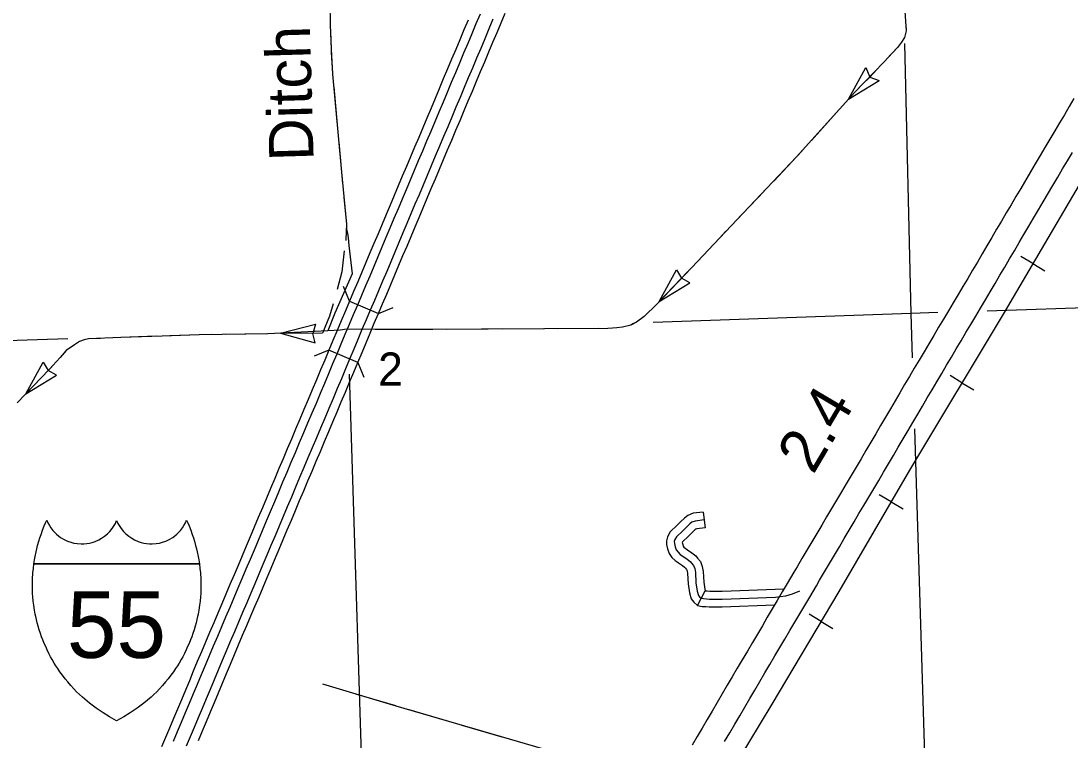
# Model space of a CAD drawing. Extents: x -117616 to 64730, y 54117 to 789866.
# Drawn here: x 63230.7 to 63430.7, y 55099.4 to 55236.4 of the extents above; entities that cross this region are included whole.
import ezdxf

# ---------------------------------------------------------------- set-up
doc = ezdxf.new("R2010")
doc.units = 0
for name, color, linetype in [('10', 7, 'Continuous'), ('19', 7, 'Continuous'), ('23', 7, 'Continuous'), ('39', 7, 'Continuous'), ('40', 7, 'Continuous'), ('43', 7, 'Continuous'), ('45', 7, 'Continuous'), ('48', 7, 'Continuous'), ('5', 7, 'Continuous')]:
    doc.layers.add(name, color=color, linetype=linetype)

msp = doc.modelspace()

# ---------------------------------------------------------------- linework, layer by layer
at = {"layer": '10'}
for points in [[(63431.46, 55221.66), (63430.55, 55220.11), (63429.63, 55218.55), (63428.72, 55217), (63427.8, 55215.46), (63426.86, 55213.89), (63425.93, 55212.32), (63425, 55210.76), (63424.08, 55209.2), (63423.15, 55207.64), (63421.3, 55204.51), (63420.38, 55202.95), (63419.46, 55201.39), (63418.54, 55199.83), (63417.63, 55198.28), (63416.71, 55196.73), (63415.78, 55195.17), (63414.86, 55193.6), (63413.95, 55192.04), (63413.04, 55190.49), (63412.12, 55188.94), (63411.21, 55187.38), (63410.29, 55185.83), (63409.37, 55184.28), (63408.44, 55182.73), (63407.51, 55181.17), (63406.58, 55179.6), (63405.65, 55178.05), (63404.72, 55176.49), (63403.79, 55174.93), (63402.87, 55173.37), (63401.94, 55171.81), (63401.01, 55170.24), (63400.1, 55168.68), (63399.18, 55167.14), (63398.27, 55165.59), (63397.37, 55164.05), (63396.45, 55162.5), (63395.53, 55160.95), (63394.6, 55159.38), (63393.66, 55157.79), (63392.72, 55156.2), (63391.79, 55154.61), (63390.86, 55153.02), (63389.92, 55151.43), (63388.98, 55149.84), (63388.05, 55148.27), (63387.11, 55146.69), (63386.17, 55145.11), (63385.24, 55143.53), (63384.3, 55141.95), (63383.36, 55140.36), (63382.42, 55138.78), (63381.48, 55137.19), (63380.54, 55135.59), (63379.6, 55133.99), (63378.66, 55132.41), (63378.06, 55131.39), (63376.78, 55129.23), (63375.84, 55127.65), (63374.88, 55126.04), (63373.93, 55124.42), (63372.98, 55122.81), (63372.05, 55121.21), (63371.1, 55119.61), (63370.15, 55117.99), (63369.19, 55116.37), (63368.23, 55114.74), (63367.28, 55113.12), (63366.32, 55111.5), (63365.36, 55109.87), (63364.39, 55108.22), (63363.43, 55106.59), (63362.48, 55104.96), (63361.52, 55103.34), (63360.56, 55101.72), (63359.6, 55100.1), (63358.65, 55098.49)], [(63364.86, 55099.17), (63365.82, 55100.79), (63366.78, 55102.43), (63367.75, 55104.06), (63368.7, 55105.69), (63369.66, 55107.33), (63370.63, 55108.96), (63371.59, 55110.58), (63372.54, 55112.21), (63373.5, 55113.83), (63374.45, 55115.45), (63375.41, 55117.07), (63376.36, 55118.68), (63377.3, 55120.28), (63378.24, 55121.89), (63379.18, 55123.49), (63380.13, 55125.09), (63381.08, 55126.68), (63382.36, 55128.84), (63382.97, 55129.86), (63383.9, 55131.45), (63384.84, 55133.05), (63385.79, 55134.64), (63386.73, 55136.23), (63387.66, 55137.82), (63388.6, 55139.4), (63389.54, 55140.98), (63390.47, 55142.56), (63391.41, 55144.14), (63392.35, 55145.72), (63393.29, 55147.3), (63394.23, 55148.89), (63395.16, 55150.48), (63396.1, 55152.08), (63397.03, 55153.66), (63397.97, 55155.25), (63398.9, 55156.83), (63399.83, 55158.4), (63400.75, 55159.95), (63401.67, 55161.5), (63402.58, 55163.05), (63403.49, 55164.6), (63404.41, 55166.15), (63405.32, 55167.7), (63406.24, 55169.26), (63407.17, 55170.82), (63408.09, 55172.37), (63409.02, 55173.93), (63409.94, 55175.49), (63410.87, 55177.05), (63411.8, 55178.61), (63412.74, 55180.17), (63413.66, 55181.72), (63414.59, 55183.28), (63415.51, 55184.84), (63416.43, 55186.4), (63417.35, 55187.96), (63418.26, 55189.51), (63419.17, 55191.07), (63420.09, 55192.63), (63421.01, 55194.18), (63421.93, 55195.73), (63422.85, 55197.3), (63423.77, 55198.86), (63424.69, 55200.41), (63425.6, 55201.97), (63427.45, 55205.09), (63428.38, 55206.65), (63429.3, 55208.21), (63430.23, 55209.77), (63431.16, 55211.33)]]:
    msp.add_lwpolyline(points, dxfattribs=at)
at = {"layer": '19'}
for points in [[(63315.96, 55236.56), (63315.17, 55234.7), (63314.39, 55232.83), (63313.61, 55230.98), (63312.82, 55229.13), (63312.03, 55227.26), (63311.23, 55225.38), (63310.45, 55223.51), (63309.67, 55221.64), (63308.89, 55219.78), (63308.11, 55217.92), (63307.32, 55216.06), (63306.53, 55214.21), (63305.74, 55212.36), (63304.96, 55210.51), (63304.18, 55208.66), (63303.4, 55206.82), (63302.63, 55204.99), (63301.87, 55203.16), (63301.1, 55201.34), (63300.32, 55199.52), (63299.55, 55197.69), (63298.78, 55195.87), (63298.01, 55194.05), (63297.23, 55192.22), (63296.46, 55190.38), (63295.69, 55188.54), (63294.91, 55186.71), (63294.13, 55184.87), (63293.35, 55183.02), (63292.55, 55181.17), (63291.76, 55179.29), (63290.97, 55177.42), (63290.19, 55175.55), (63289.41, 55173.68), (63288.62, 55171.8), (63287.83, 55169.93), (63287.04, 55168.05), (63286.25, 55166.17), (63285.46, 55164.29), (63284.66, 55162.41), (63283.86, 55160.53), (63283.07, 55158.65), (63282.27, 55156.77), (63281.47, 55154.89), (63280.67, 55153), (63279.88, 55151.13), (63279.08, 55149.25), (63278.3, 55147.37), (63277.51, 55145.51), (63276.73, 55143.66), (63275.96, 55141.82), (63275.18, 55139.98), (63274.41, 55138.16), (63273.64, 55136.34), (63272.87, 55134.53), (63272.1, 55132.71), (63271.33, 55130.89), (63270.56, 55129.07), (63269.79, 55127.25), (63269.01, 55125.41), (63268.23, 55123.58), (63267.45, 55121.74), (63266.66, 55119.91), (63265.88, 55118.07), (63265.1, 55116.22), (63264.33, 55114.39), (63263.57, 55112.56), (63262.81, 55110.74), (63262.05, 55108.93), (63261.29, 55107.12), (63260.53, 55105.32), (63259.77, 55103.52), (63259.01, 55101.72), (63258.25, 55099.92), (63257.49, 55098.12)], [(63259.82, 55099.25), (63260.58, 55101.05), (63261.34, 55102.85), (63262.1, 55104.66), (63262.86, 55106.46), (63263.62, 55108.27), (63264.38, 55110.09), (63265.14, 55111.91), (63265.9, 55113.73), (63266.67, 55115.57), (63267.44, 55117.4), (63268.23, 55119.24), (63269.01, 55121.07), (63269.79, 55122.91), (63270.58, 55124.75), (63271.35, 55126.58), (63272.13, 55128.41), (63272.9, 55130.23), (63273.67, 55132.05), (63274.44, 55133.86), (63275.21, 55135.68), (63275.98, 55137.5), (63276.75, 55139.32), (63277.52, 55141.16), (63278.3, 55143), (63279.08, 55144.85), (63279.86, 55146.72), (63280.65, 55148.59), (63281.44, 55150.46), (63282.24, 55152.34), (63283.03, 55154.22), (63283.83, 55156.11), (63284.63, 55157.99), (63285.43, 55159.87), (63286.23, 55161.75), (63287.02, 55163.63), (63287.82, 55165.51), (63288.61, 55167.39), (63289.4, 55169.27), (63290.19, 55171.15), (63290.98, 55173.02), (63291.76, 55174.89), (63292.54, 55176.76), (63293.33, 55178.63), (63294.12, 55180.5), (63294.91, 55182.36), (63295.7, 55184.2), (63296.48, 55186.04), (63297.26, 55187.88), (63298.03, 55189.72), (63298.8, 55191.56), (63299.57, 55193.39), (63300.35, 55195.21), (63301.12, 55197.03), (63301.89, 55198.86), (63302.66, 55200.68), (63303.43, 55202.5), (63304.2, 55204.33), (63304.97, 55206.16), (63305.74, 55208), (63306.52, 55209.84), (63307.31, 55211.69), (63308.1, 55213.55), (63308.89, 55215.4), (63309.67, 55217.26), (63310.46, 55219.12), (63311.24, 55220.99), (63312.02, 55222.85), (63312.8, 55224.72), (63313.59, 55226.6), (63314.38, 55228.46), (63315.17, 55230.32), (63315.96, 55232.17), (63316.74, 55234.04), (63317.52, 55235.9), (63318.31, 55237.75)], [(63320.7, 55236.73), (63319.92, 55234.88), (63319.14, 55233.03), (63318.35, 55231.17), (63317.57, 55229.3), (63316.78, 55227.44), (63315.98, 55225.58), (63315.2, 55223.72), (63314.42, 55221.85), (63313.64, 55219.98), (63312.85, 55218.11), (63312.07, 55216.25), (63311.28, 55214.38), (63310.49, 55212.53), (63309.7, 55210.68), (63308.92, 55208.83), (63308.14, 55206.99), (63307.37, 55205.15), (63306.6, 55203.32), (63305.83, 55201.49), (63305.06, 55199.66), (63304.28, 55197.84), (63303.51, 55196.02), (63302.74, 55194.2), (63301.97, 55192.37), (63301.2, 55190.55), (63300.43, 55188.71), (63299.65, 55186.87), (63298.87, 55185.03), (63298.09, 55183.18), (63297.3, 55181.34), (63296.51, 55179.48), (63295.72, 55177.63), (63294.94, 55175.76), (63294.16, 55173.89), (63293.37, 55172.01), (63292.59, 55170.14), (63291.8, 55168.26), (63291.01, 55166.38), (63290.21, 55164.5), (63289.42, 55162.61), (63288.62, 55160.73), (63287.82, 55158.85), (63287.02, 55156.97), (63286.22, 55155.09), (63285.43, 55153.21), (63284.63, 55151.33), (63283.84, 55149.45), (63283.04, 55147.58), (63282.26, 55145.71), (63281.48, 55143.85), (63280.7, 55141.99), (63279.92, 55140.15), (63279.15, 55138.31), (63278.37, 55136.48), (63277.6, 55134.66), (63276.83, 55132.85), (63276.06, 55131.03), (63275.29, 55129.22), (63274.52, 55127.39), (63273.75, 55125.57), (63272.97, 55123.73), (63272.19, 55121.89), (63271.4, 55120.05), (63270.62, 55118.22), (63269.83, 55116.39), (63269.06, 55114.56), (63268.3, 55112.73), (63267.54, 55110.91), (63266.78, 55109.08), (63266.02, 55107.27), (63265.26, 55105.45), (63264.5, 55103.65), (63263.73, 55101.84), (63262.97, 55100.04), (63262.21, 55098.24)], [(63264.54, 55099.38), (63265.3, 55101.18), (63266.06, 55102.99), (63266.82, 55104.8), (63267.59, 55106.61), (63268.35, 55108.43), (63269.11, 55110.25), (63269.87, 55112.08), (63270.63, 55113.9), (63271.4, 55115.72), (63272.18, 55117.55), (63272.97, 55119.39), (63273.75, 55121.23), (63274.53, 55123.07), (63275.31, 55124.9), (63276.09, 55126.73), (63276.86, 55128.55), (63277.63, 55130.37), (63278.4, 55132.18), (63279.17, 55134), (63279.94, 55135.82), (63280.71, 55137.65), (63281.49, 55139.49), (63282.26, 55141.33), (63283.04, 55143.19), (63283.83, 55145.05), (63284.61, 55146.92), (63285.4, 55148.79), (63286.2, 55150.67), (63286.99, 55152.55), (63287.79, 55154.42), (63288.59, 55156.3), (63289.39, 55158.19), (63290.18, 55160.07), (63290.98, 55161.95), (63291.78, 55163.84), (63292.57, 55165.72), (63293.37, 55167.6), (63294.15, 55169.48), (63294.94, 55171.36), (63295.73, 55173.23), (63296.51, 55175.1), (63297.29, 55176.97), (63298.07, 55178.82), (63298.86, 55180.67), (63299.65, 55182.52), (63300.44, 55184.37), (63301.22, 55186.21), (63301.99, 55188.05), (63302.76, 55189.89), (63303.53, 55191.71), (63304.31, 55193.53), (63305.08, 55195.36), (63305.85, 55197.18), (63306.62, 55199), (63307.4, 55200.83), (63308.17, 55202.66), (63308.94, 55204.5), (63309.71, 55206.33), (63310.48, 55208.17), (63311.26, 55210.01), (63312.05, 55211.86), (63312.84, 55213.72), (63313.63, 55215.59), (63314.42, 55217.45), (63315.21, 55219.33), (63315.99, 55221.19), (63316.77, 55223.06), (63317.55, 55224.92), (63318.34, 55226.78), (63319.13, 55228.64), (63319.92, 55230.51), (63320.7, 55232.37), (63321.49, 55234.22), (63322.27, 55236.07), (63323.05, 55237.91)]]:
    msp.add_lwpolyline(points, dxfattribs=at)
at = {"layer": '23'}
for points in [[(63233.18, 55133), (63233.3, 55133.75), (63233.42, 55134.42), (63233.6, 55135.28), (63233.73, 55135.84), (63233.89, 55136.5), (63234.11, 55137.29), (63234.32, 55137.94), (63234.54, 55138.61), (63234.84, 55139.44), (63235.15, 55140.22), (63235.41, 55140.82), (63235.62, 55141.29), (63235.85, 55140.78), (63236.12, 55140.29), (63236.42, 55139.85), (63236.8, 55139.35), (63237.1, 55139.01), (63237.48, 55138.65), (63237.86, 55138.33), (63238.27, 55138.03), (63238.93, 55137.64), (63239.6, 55137.33), (63240.2, 55137.11), (63240.8, 55136.96), (63241.45, 55136.85), (63242.2, 55136.8), (63242.69, 55136.81), (63243.25, 55136.87), (63243.76, 55136.95), (63244.3, 55137.08), (63244.84, 55137.26), (63245.57, 55137.58), (63246.07, 55137.87), (63246.66, 55138.27), (63247.22, 55138.74), (63247.63, 55139.15), (63248.09, 55139.72), (63248.48, 55140.3), (63248.71, 55140.7), (63248.95, 55141.23)], [(63248.95, 55141.23), (63249.2, 55140.7), (63249.43, 55140.3), (63249.82, 55139.72), (63250.28, 55139.15), (63250.69, 55138.74), (63251.25, 55138.27), (63251.84, 55137.87), (63252.34, 55137.58), (63253.07, 55137.26), (63253.61, 55137.08), (63254.15, 55136.95), (63254.65, 55136.87), (63255.22, 55136.81), (63255.71, 55136.8), (63256.46, 55136.85), (63257.1, 55136.96), (63257.7, 55137.11), (63258.31, 55137.33), (63258.98, 55137.64), (63259.64, 55138.03), (63260.05, 55138.33), (63260.43, 55138.65), (63260.8, 55139.01), (63261.11, 55139.35), (63261.49, 55139.85), (63261.79, 55140.29), (63262.05, 55140.78), (63262.29, 55141.29), (63262.5, 55140.82), (63262.76, 55140.22), (63263.07, 55139.44), (63263.37, 55138.61), (63263.59, 55137.94), (63263.8, 55137.29), (63264.01, 55136.5), (63264.18, 55135.84), (63264.31, 55135.28), (63264.49, 55134.42), (63264.61, 55133.75), (63264.72, 55133)], [(63248.95, 55103.12), (63247.57, 55103.86), (63246.36, 55104.59), (63245.02, 55105.5), (63243.77, 55106.44), (63242.41, 55107.6), (63241.9, 55108.08), (63241.32, 55108.64), (63240.78, 55109.2), (63240.19, 55109.84), (63239.62, 55110.51), (63239.13, 55111.11), (63238.61, 55111.79), (63238.14, 55112.44), (63237.73, 55113.05), (63237.37, 55113.6), (63237.07, 55114.08), (63236.67, 55114.76), (63236.37, 55115.31), (63236.03, 55115.95), (63235.7, 55116.62), (63235.42, 55117.24), (63235.16, 55117.83), (63234.88, 55118.5), (63234.65, 55119.12), (63234.42, 55119.76), (63234.2, 55120.44), (63233.99, 55121.13), (63233.81, 55121.79), (63233.66, 55122.42), (63233.53, 55122.98), (63233.44, 55123.39), (63233.29, 55124.19), (63233.15, 55125.12), (63233.05, 55125.89), (63232.98, 55126.71), (63232.94, 55127.37), (63232.91, 55128.2), (63232.9, 55128.98), (63232.91, 55129.85), (63232.94, 55130.42), (63232.97, 55130.94), (63232.99, 55131.27), (63233.08, 55132.13), (63233.18, 55133)], [(63233.18, 55133), (63264.72, 55133)], [(63264.72, 55133), (63233.18, 55133)], [(63264.72, 55133), (63264.83, 55132.13), (63264.92, 55131.27), (63264.94, 55130.94), (63264.97, 55130.42), (63265, 55129.85), (63265.01, 55128.98), (63265, 55128.2), (63264.97, 55127.37), (63264.93, 55126.71), (63264.86, 55125.89), (63264.76, 55125.12), (63264.62, 55124.19), (63264.47, 55123.39), (63264.38, 55122.98), (63264.25, 55122.42), (63264.1, 55121.79), (63263.92, 55121.13), (63263.71, 55120.44), (63263.49, 55119.76), (63263.26, 55119.12), (63263.02, 55118.5), (63262.75, 55117.83), (63262.49, 55117.24), (63262.21, 55116.62), (63261.88, 55115.95), (63261.54, 55115.31), (63261.24, 55114.76), (63260.84, 55114.08), (63260.54, 55113.6), (63260.18, 55113.05), (63259.77, 55112.44), (63259.3, 55111.79), (63258.78, 55111.11), (63258.29, 55110.51), (63257.72, 55109.84), (63257.13, 55109.2), (63256.59, 55108.64), (63256.01, 55108.08), (63255.5, 55107.6), (63254.14, 55106.44), (63252.89, 55105.5), (63251.55, 55104.59), (63250.34, 55103.86), (63248.95, 55103.12)]]:
    msp.add_lwpolyline(points, dxfattribs=at)
at = {"layer": '39'}
for p, q in [((63293.35, 55183.02), (63292.22, 55185.8)), ((63293.35, 55183.02), (63298.87, 55180.69)), ((63298.87, 55180.69), (63301.65, 55181.82)), ((63289.41, 55173.67), (63286.63, 55172.54)), ((63294.94, 55171.36), (63289.41, 55173.67)), ((63294.94, 55171.36), (63296.08, 55168.58))]:
    msp.add_line(p, q, dxfattribs=at)
at = {"layer": '40'}
for p, q in [((63423.61, 55190.18), (63421.34, 55191.52)), ((63423.61, 55190.18), (63425.88, 55188.84)), ((63410.1, 55167.5), (63407.84, 55168.85)), ((63410.1, 55167.5), (63412.37, 55166.14)), ((63396.6, 55144.81), (63394.32, 55146.14)), ((63396.6, 55144.81), (63398.88, 55143.48)), ((63383.24, 55122.04), (63380.97, 55123.39)), ((63383.24, 55122.04), (63385.51, 55120.69))]:
    msp.add_line(p, q, dxfattribs=at)
for points in [[(63497.11, 55314.94), (63494.89, 55311.15), (63488.19, 55299.73), (63486.63, 55297.09), (63484.35, 55293.36), (63480.84, 55287.75), (63474.86, 55277.55), (63472.91, 55274.32), (63459.75, 55252.17), (63453.09, 55240.87), (63451.71, 55238.38), (63449.77, 55234.97), (63444.13, 55224.89), (63441.27, 55220.19), (63436.54, 55212.09), (63418.12, 55180.88), (63400.11, 55150.82), (63386.64, 55127.75), (63373.86, 55106.28), (63362.71, 55087.83), (63354.73, 55074.34)], [(63497.11, 55314.94), (63494.89, 55311.15), (63488.19, 55299.73), (63486.63, 55297.09), (63484.35, 55293.36), (63480.84, 55287.75), (63474.86, 55277.55), (63472.91, 55274.32), (63459.75, 55252.17), (63453.09, 55240.87), (63451.71, 55238.38), (63449.77, 55234.97), (63444.13, 55224.89), (63441.27, 55220.19), (63436.54, 55212.09), (63418.12, 55180.88), (63400.11, 55150.82), (63386.64, 55127.75), (63373.86, 55106.28), (63362.71, 55087.83), (63355.07, 55074.27)]]:
    msp.add_lwpolyline(points, dxfattribs=at)
at = {"layer": '43'}
for p, q in [((63388.47, 55221.5), (63391.75, 55227.53)), ((63391.75, 55227.53), (63392.53, 55225.72)), ((63388.47, 55221.5), (63394.33, 55225.08)), ((63392.53, 55225.72), (63394.33, 55225.08)), ((63352.4, 55182.95), (63355.68, 55188.98)), ((63355.68, 55188.98), (63356.63, 55187.42)), ((63352.4, 55182.95), (63358.25, 55186.53)), ((63358.25, 55186.53), (63356.65, 55187.4)), ((63280.21, 55176.95), (63286.86, 55178.65)), ((63286.86, 55178.65), (63286.36, 55176.89)), ((63280.21, 55176.95), (63286.82, 55175.09)), ((63286.82, 55175.09), (63286.36, 55176.86)), ((63231.62, 55165.37), (63234.92, 55171.39)), ((63234.92, 55171.39), (63235.87, 55169.83)), ((63231.62, 55165.37), (63237.49, 55168.94)), ((63237.49, 55168.94), (63235.89, 55169.81))]:
    msp.add_line(p, q, dxfattribs=at)
for points in [[(63288.29, 55314.94), (63288.51, 55306.96), (63288.93, 55288.45), (63289.12, 55283.22), (63289.02, 55278.57), (63289.31, 55256.35), (63289.59, 55239.99), (63289.66, 55235.68), (63289.82, 55231.01), (63290.13, 55226.27), (63291.84, 55207.62), (63292.74, 55197.67), (63292.76, 55196.74), (63292.95, 55196.01), (63293.07, 55195.09), (63293.21, 55193.63), (63293.85, 55188.22), (63290.53, 55180.74), (63289.19, 55177.36)], [(63399.14, 55239.17), (63399.47, 55234.52), (63399.14, 55233.23), (63398.6, 55232.38), (63397.83, 55231.38), (63395.18, 55228.55), (63389.7, 55222.86), (63378.56, 55210.5), (63363.85, 55195.01), (63358.58, 55189.45), (63351.95, 55182.47), (63349.5, 55180.14), (63348.07, 55179.04), (63346.95, 55178.47), (63345.36, 55178.11), (63344.3, 55177.96), (63342.58, 55177.85), (63306.43, 55177.62), (63298.26, 55177.62), (63292.82, 55177.69), (63291.54, 55177.49), (63289.19, 55177.36), (63277.76, 55176.84), (63264.68, 55176.62), (63257.61, 55176.39), (63249.76, 55176.13), (63243.57, 55175.85), (63242.73, 55175.67), (63241.87, 55175.36), (63240.89, 55174.69), (63239.35, 55173.65), (63238.19, 55172.28), (63236.08, 55170.03), (63229.97, 55163.64)], [(63399.14, 55239.17), (63399.47, 55234.52), (63399.14, 55233.23), (63398.6, 55232.38), (63397.83, 55231.38), (63395.18, 55228.55), (63389.7, 55222.86), (63378.56, 55210.5), (63363.85, 55195.01), (63358.58, 55189.45), (63351.95, 55182.47), (63349.5, 55180.14), (63348.07, 55179.04), (63346.95, 55178.47), (63345.36, 55178.11), (63344.3, 55177.96), (63342.58, 55177.85), (63306.43, 55177.62), (63298.26, 55177.62), (63292.82, 55177.69), (63291.54, 55177.49), (63289.19, 55177.36), (63277.76, 55176.84), (63264.68, 55176.62), (63257.61, 55176.39), (63249.76, 55176.13), (63243.57, 55175.85), (63242.73, 55175.67), (63241.87, 55175.36), (63240.89, 55174.69), (63239.35, 55173.65), (63238.19, 55172.28), (63236.08, 55170.03), (63229.97, 55163.64)], [(63289.71, 55234.38), (63289.82, 55231.01), (63289.86, 55230.42)], [(63399.38, 55235.78), (63399.47, 55234.52), (63399.14, 55233.23), (63398.6, 55232.38), (63397.83, 55231.38), (63395.74, 55229.15)], [(63289.86, 55230.42), (63290.12, 55226.47)], [(63393.92, 55227.24), (63392.53, 55225.72), (63391.17, 55224.39)], [(63391.17, 55224.39), (63389.7, 55222.86), (63388.47, 55221.5)], [(63290.36, 55223.84), (63291.08, 55215.95)], [(63386.7, 55219.54), (63381.4, 55213.65)], [(63291.32, 55213.33), (63291.84, 55207.62), (63292.03, 55205.44)], [(63379.64, 55211.69), (63378.56, 55210.5), (63374.21, 55205.92)], [(63292.27, 55202.81), (63292.74, 55197.67), (63292.62, 55194.75), (63292.63, 55194.6)], [(63372.4, 55204), (63366.94, 55198.26)], [(63365.12, 55196.35), (63363.85, 55195.01), (63359.67, 55190.6)], [(63292.33, 55192.59), (63291.86, 55188.65), (63290.97, 55185.28)], [(63357.86, 55188.68), (63352.4, 55182.95)], [(63290.21, 55182.52), (63289.52, 55180.18), (63288.19, 55176.97)], [(63350.51, 55181.1), (63349.5, 55180.14), (63348.07, 55179.04), (63347.39, 55178.7)], [(63347.39, 55178.7), (63346.95, 55178.47), (63345.36, 55178.11), (63344.3, 55177.96), (63343.54, 55177.91)], [(63256.46, 55176.35), (63249.76, 55176.13), (63248.54, 55176.08)], [(63267.01, 55176.66), (63264.68, 55176.62), (63259.09, 55176.44)], [(63277.57, 55176.84), (63269.65, 55176.7)], [(63286.36, 55176.89), (63280.21, 55176.95)], [(63288.19, 55176.97), (63286.36, 55176.89)], [(63309.22, 55177.64), (63306.43, 55177.62), (63301.3, 55177.62)], [(63319.78, 55177.71), (63311.86, 55177.66)], [(63330.34, 55177.78), (63322.42, 55177.73)], [(63340.9, 55177.84), (63332.98, 55177.79)], [(63245.9, 55175.95), (63243.57, 55175.85), (63242.73, 55175.67), (63241.87, 55175.36), (63240.89, 55174.69), (63239.35, 55173.65), (63238.85, 55173.07)], [(63237.09, 55171.11), (63236.08, 55170.03), (63231.62, 55165.37)], [(63288.18, 55110.14), (63302.18, 55105.97), (63330.31, 55097.73), (63333.12, 55097), (63335.03, 55096.58), (63338.54, 55095.7), (63341.4, 55095.01), (63345.27, 55093.85), (63347.92, 55092.82), (63349.95, 55091.96), (63351.49, 55091.3), (63352.84, 55090.59), (63354.11, 55089.85), (63355.66, 55089.25), (63356.61, 55089.01), (63359.11, 55088.76), (63360.09, 55088.61), (63361.22, 55088.49), (63362.29, 55088.2), (63362.29, 55088.04), (63363.64, 55087.17)], [(63288.18, 55110.14), (63291.98, 55109.01)], [(63294.51, 55108.26), (63302.1, 55106)], [(63304.63, 55105.25), (63312.23, 55103.03)], [(63314.77, 55102.28), (63322.37, 55100.06)]]:
    msp.add_lwpolyline(points, dxfattribs=at)
at = {"layer": '45'}
for p, q in [((63360.77, 55142.85), (63361.13, 55139.87)), ((63359.7, 55125.08), (63361.17, 55127.86))]:
    msp.add_line(p, q, dxfattribs=at)
for points in [[(63360.77, 55142.85), (63358.85, 55142.62), (63357.83, 55142.22), (63357.22, 55141.72), (63356.46, 55141), (63355.84, 55140.34), (63354.46, 55139.1), (63353.95, 55138.16), (63353.77, 55137.39), (63353.8, 55136.69), (63353.99, 55135.85), (63354.29, 55134.98), (63354.82, 55134.23), (63355.42, 55133.65), (63355.8, 55133.38)], [(63360.95, 55141.36), (63359.22, 55141.15), (63358.6, 55140.91), (63358.22, 55140.6), (63357.52, 55139.94), (63356.88, 55139.26), (63355.66, 55138.15), (63355.36, 55137.62), (63355.27, 55137.25), (63355.29, 55136.89), (63355.43, 55136.27), (63355.64, 55135.68), (63355.97, 55135.21), (63356.38, 55134.81), (63356.92, 55134.43), (63357.71, 55133.9), (63358.29, 55133.45), (63358.55, 55133.12), (63358.93, 55132.67), (63359.15, 55132.1), (63359.29, 55131.35), (63359.39, 55129.35), (63359.62, 55127.82), (63359.86, 55126.99), (63360.07, 55126.72), (63360.36, 55126.47), (63360.8, 55126.39), (63361.96, 55126.3), (63364.4, 55126.3), (63374.56, 55126.67), (63375.46, 55126.78), (63376.53, 55126.91), (63377.78, 55127.26), (63379.2, 55127.85)], [(63361.13, 55139.87), (63359.59, 55139.68), (63359.36, 55139.6), (63359.21, 55139.47), (63358.59, 55138.88), (63357.93, 55138.19), (63356.85, 55137.21), (63356.78, 55137.09), (63356.78, 55137.09), (63356.87, 55136.68), (63356.98, 55136.37), (63357.11, 55136.19), (63357.34, 55135.97), (63357.54, 55135.83)], [(63357.54, 55135.83), (63357.77, 55135.67), (63358.6, 55135.11), (63359.35, 55134.52), (63359.7, 55134.08), (63360.23, 55133.45), (63360.6, 55132.51), (63360.78, 55131.53), (63360.89, 55129.5), (63361.09, 55128.15), (63361.17, 55127.86), (63361.51, 55127.84)], [(63355.8, 55133.38), (63356.07, 55133.2), (63356.83, 55132.68), (63357.22, 55132.37), (63357.39, 55132.17), (63357.62, 55131.9), (63357.7, 55131.68), (63357.8, 55131.17), (63357.9, 55129.2), (63358.15, 55127.5), (63358.5, 55126.31), (63358.98, 55125.67), (63359.7, 55125.08), (63360.59, 55124.9), (63361.29, 55124.85)], [(63361.51, 55127.84), (63362.01, 55127.8), (63364.37, 55127.8), (63376.18, 55128.23)], [(63361.29, 55124.85), (63361.9, 55124.8), (63364.42, 55124.8), (63374.36, 55125.16)]]:
    msp.add_lwpolyline(points, dxfattribs=at)
at = {"layer": '5'}
for points in [[(63400.43, 55180.69), (63399.21, 55232.09)], [(63400.43, 55180.69), (63351.24, 55178.96)], [(63405.51, 55180.85), (63400.43, 55180.69)], [(63400.69, 55172.25), (63400.43, 55180.69)], [(63437.32, 55181.86), (63414.9, 55181.15)], [(63239.67, 55175.88), (63187.33, 55174.12)], [(63293.25, 55169.16), (63296.28, 55074.54)], [(63403.69, 55075.86), (63401.11, 55158.72)]]:
    msp.add_lwpolyline(points, dxfattribs=at)

# ---------------------------------------------------------------- texts
at = {"layer": '23'}
msp.add_text('55', height=12.704, dxfattribs=at).set_placement((63239.46, 55115.09))
at = {"layer": '39'}
msp.add_text('2', height=6.34, dxfattribs=at).set_placement((63298.79, 55166.92))
at = {"layer": '43'}
msp.add_text('Ditch', height=8.448, rotation=91.6737, dxfattribs=at).set_placement((63286.52, 55209.83))
at = {"layer": '48'}
msp.add_text('2.4', height=8.448, rotation=59.4056, dxfattribs=at).set_placement((63381.74, 55149.83))

doc.saveas('drawing.dxf')
